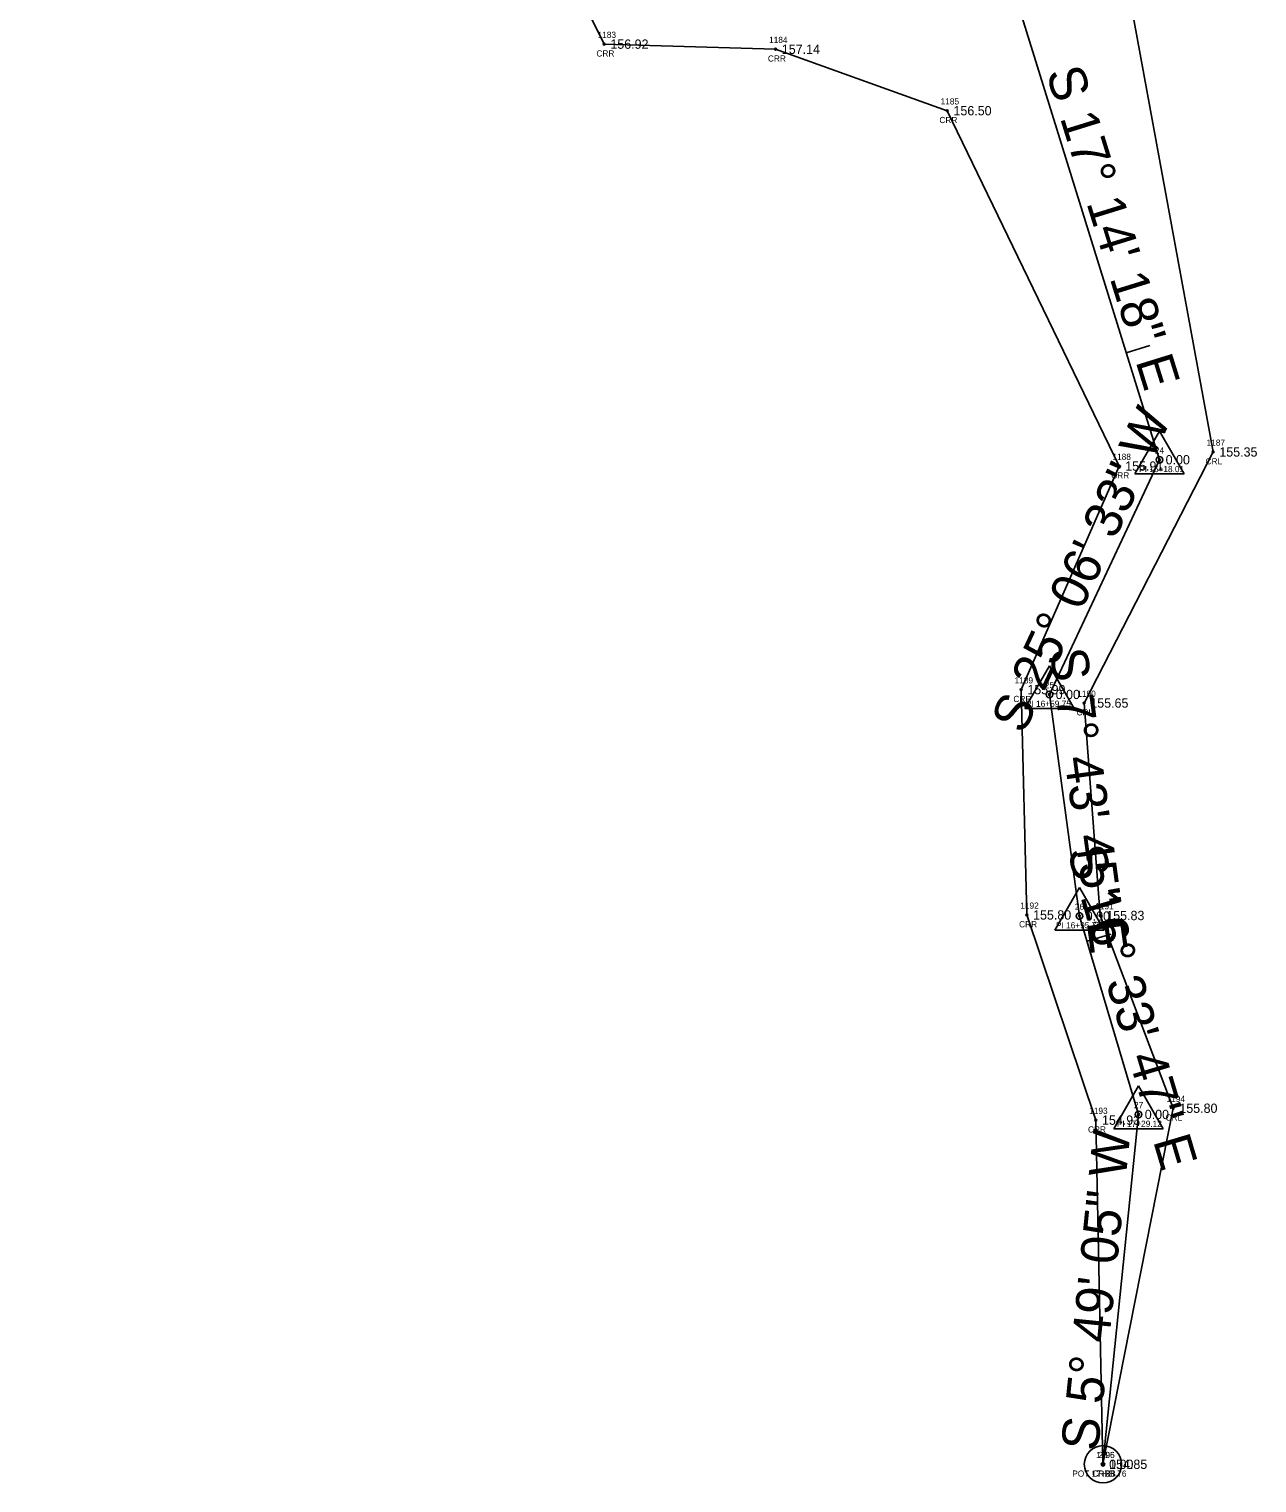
# Model space of a CAD drawing. Extents: x 2380345 to 2383438, y 1028917 to 1030787.
# Drawn here: x 2382160.7 to 2382358.5, y 1029958.9 to 1030193.1 of the extents above; entities that cross this region are included whole.
import ezdxf

# ---------------------------------------------------------------- set-up
doc = ezdxf.new("R2010")
doc.units = 0
for name, color, linetype in [('RD_EX_H2O', 7, 'Continuous'), ('RD_EX_H2O_txCode', 7, 'Continuous'), ('RD_EX_TX_H2O_ELEV', 7, 'Continuous'), ('RD_HC_Cl', 7, 'Continuous'), ('RD_HC_Data', 7, 'Continuous'), ('RD_HC_Data_Tic', 7, 'Continuous'), ('RD_HC_Survey_ELEV', 7, 'Continuous'), ('RD_HC_txCode', 7, 'Continuous'), ('RD_SMD_Locator', 7, 'Continuous')]:
    doc.layers.add(name, color=color, linetype=linetype)

msp = doc.modelspace()

# ---------------------------------------------------------------- linework, layer by layer
at = {"layer": 'RD_EX_H2O'}
for points in [[(2382228.76, 1030407.08), (2382229.33, 1030393.42), (2382229.44, 1030376.02), (2382235.1, 1030355.5), (2382240.51, 1030349.49), (2382245.56, 1030316.86), (2382248.97, 1030289.05), (2382238.04, 1030280.56), (2382242.49, 1030255.05), (2382259.38, 1030214.05), (2382335.14, 1030213.97), (2382351.43, 1030124.97), (2382330.65, 1030084.53), (2382333.22, 1030050.31), (2382344.99, 1030019.27), (2382333.68, 1029961.92)], [(2382160.73, 1030399.39), (2382197.66, 1030393.98), (2382201.16, 1030391.22), (2382207.75, 1030374.4), (2382216.83, 1030343.34), (2382214.66, 1030277.58), (2382224.95, 1030248.16), (2382253.35, 1030190.66), (2382280.97, 1030189.84), (2382308.61, 1030179.94), (2382336.27, 1030122.7), (2382320.51, 1030086.69), (2382321.43, 1030050.4), (2382332.53, 1030017.35), (2382333.68, 1029961.92)]]:
    msp.add_lwpolyline(points, dxfattribs=at)
at = {"layer": 'RD_HC_Cl'}
for p, q in [((2382320.42, 1030195.79), (2382342.78, 1030123.72)), ((2382342.78, 1030123.72), (2382325.07, 1030085.92)), ((2382325.07, 1030085.92), (2382329.91, 1030050.23)), ((2382329.91, 1030050.23), (2382339.42, 1030018.27)), ((2382339.42, 1030018.27), (2382333.68, 1029961.92))]:
    msp.add_line(p, q, dxfattribs=at)
at = {"layer": 'RD_HC_Data'}
for p, q in [((2382338.81, 1030121.43), (2382342.78, 1030128.31)), ((2382342.78, 1030128.31), (2382346.75, 1030121.43)), ((2382338.81, 1030121.43), (2382346.75, 1030121.43)), ((2382321.1, 1030083.63), (2382325.07, 1030090.51)), ((2382325.07, 1030090.51), (2382329.04, 1030083.63)), ((2382321.1, 1030083.63), (2382329.04, 1030083.63)), ((2382325.94, 1030047.94), (2382329.91, 1030054.82)), ((2382329.91, 1030054.82), (2382333.88, 1030047.94)), ((2382325.94, 1030047.94), (2382333.88, 1030047.94)), ((2382335.45, 1030015.97), (2382339.42, 1030022.85)), ((2382339.42, 1030022.85), (2382343.39, 1030015.97)), ((2382335.45, 1030015.97), (2382343.39, 1030015.97))]:
    msp.add_line(p, q, dxfattribs=at)
for centre, radius in [((2382342.78, 1030123.72), 0.529), ((2382325.07, 1030085.92), 0.529), ((2382329.91, 1030050.23), 0.529), ((2382339.42, 1030018.27), 0.529), ((2382333.68, 1029961.92), 3), ((2382333.68, 1029961.92), 0.282)]:
    msp.add_circle(centre, radius, dxfattribs=at)
at = {"layer": 'RD_HC_Data_Tic'}
for p, q in [((2382337.44, 1030140.92), (2382341.26, 1030142.1)), ((2382331.12, 1030046.17), (2382334.95, 1030047.31))]:
    msp.add_line(p, q, dxfattribs=at)
at = {"layer": 'RD_SMD_Locator'}
for centre in [(2382253.35, 1030190.66), (2382280.97, 1030189.84), (2382308.61, 1030179.94), (2382342.78, 1030123.72), (2382351.43, 1030124.97), (2382336.27, 1030122.7), (2382320.51, 1030086.69), (2382325.07, 1030085.92), (2382330.65, 1030084.53), (2382321.43, 1030050.4), (2382329.91, 1030050.23), (2382333.22, 1030050.31), (2382339.42, 1030018.27), (2382344.99, 1030019.27), (2382332.53, 1030017.35), (2382333.68, 1029961.92), (2382333.68, 1029961.92), (2382333.68, 1029961.92)]:
    msp.add_circle(centre, 0.15, dxfattribs=at)

# ---------------------------------------------------------------- texts
at = {"layer": 'RD_EX_H2O_txCode'}
for s, p in [('1183', (2382252.29, 1030191.66)), ('1184', (2382279.91, 1030190.84)), ('CRR', (2382252.1, 1030188.66)), ('CRR', (2382279.72, 1030187.84)), ('1185', (2382307.54, 1030180.94)), ('CRR', (2382307.35, 1030177.94)), ('1187', (2382350.37, 1030125.97)), ('1188', (2382335.21, 1030123.7)), ('CRL', (2382350.2, 1030122.97)), ('CRR', (2382335.02, 1030120.7)), ('1189', (2382319.45, 1030087.69)), ('CRR', (2382319.26, 1030084.69)), ('1190', (2382329.55, 1030085.53)), ('CRL', (2382329.42, 1030082.53)), ('1192', (2382320.37, 1030051.4)), ('1191', (2382332.44, 1030051.31)), ('CRR', (2382320.18, 1030048.4)), ('CRL', (2382331.99, 1030048.31)), ('1194', (2382343.92, 1030020.27)), ('1193', (2382331.46, 1030018.35)), ('CRL', (2382343.76, 1030017.27)), ('CRR', (2382331.27, 1030015.35)), ('1196', (2382332.59, 1029962.92)), ('1195', (2382332.61, 1029962.92)), ('CRRB', (2382331.95, 1029959.92)), ('CRLB', (2382331.98, 1029959.92))]:
    msp.add_text(s, height=1, dxfattribs=at).set_placement(p)
at = {"layer": 'RD_EX_TX_H2O_ELEV'}
for s, p in [('156.92', (2382254.35, 1030189.91)), ('157.14', (2382281.97, 1030189.09)), ('156.50', (2382309.61, 1030179.19)), ('155.35', (2382352.43, 1030124.22)), ('155.91', (2382337.27, 1030121.95)), ('155.99', (2382321.51, 1030085.94)), ('155.65', (2382331.65, 1030083.78)), ('155.80', (2382322.43, 1030049.65)), ('155.83', (2382334.22, 1030049.56)), ('154.93', (2382333.53, 1030016.6)), ('155.80', (2382345.99, 1030018.52)), ('154.85', (2382334.68, 1029961.17)), ('154.85', (2382334.68, 1029961.17))]:
    msp.add_text(s, height=1.5, dxfattribs=at).set_placement(p)
at = {"layer": 'RD_HC_Data'}
for s, rotation, p in [('S 17%%d 14\' 18" E', 287.2384, (2382324.48, 1030186.07)), ('S 25%%d 06\' 33" W', 64.8909, (2382320.89, 1030079.36)), ('S 7%%d 43\' 45" E', 277.7291, (2382325.11, 1030093.02)), ('S 16%%d 33\' 47" E', 286.563, (2382327.86, 1030060.65)), ('S 5%%d 49\' 05" W', 84.182, (2382332.88, 1029963.95))]:
    msp.add_text(s, height=6, rotation=rotation, dxfattribs=at).set_placement(p)
at = {"layer": 'RD_HC_Survey_ELEV'}
for p in [(2382343.78, 1030122.97), (2382326.07, 1030085.17), (2382330.91, 1030049.48), (2382340.42, 1030017.52), (2382334.68, 1029961.17)]:
    msp.add_text('0.00', height=1.5, dxfattribs=at).set_placement(p)
at = {"layer": 'RD_HC_txCode'}
for s, p in [('24', (2382342.05, 1030124.72)), ('PI 16+18.01', (2382339.51, 1030121.72)), ('25', (2382324.34, 1030086.92)), ('PI 16+59.75', (2382321.27, 1030083.92)), ('26', (2382329.16, 1030051.23)), ('PI 16+95.77', (2382326.11, 1030048.23)), ('27', (2382338.69, 1030019.27)), ('PI 17+29.12', (2382335.92, 1030016.27)), ('28', (2382332.95, 1029962.92)), ('POT 17+85.76', (2382328.74, 1029959.92))]:
    msp.add_text(s, height=1, dxfattribs=at).set_placement(p)

doc.saveas('drawing.dxf')
